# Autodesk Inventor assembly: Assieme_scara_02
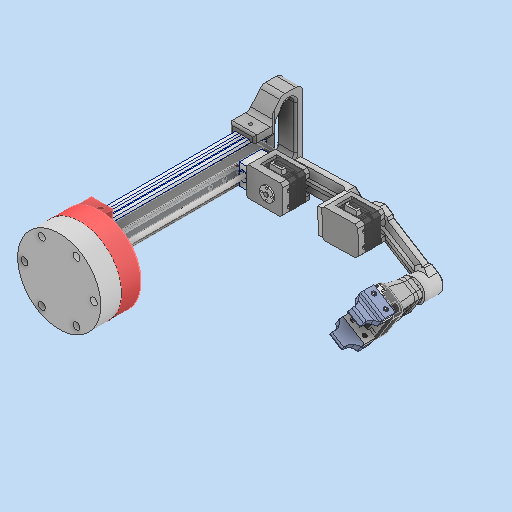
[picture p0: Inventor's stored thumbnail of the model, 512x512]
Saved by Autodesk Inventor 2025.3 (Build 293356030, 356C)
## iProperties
Created: 2025-11
Part Number: Assieme_scara_02
Document SubType Name: Assembly
Designer: Ryzen5700u
Title: Assieme_scara_03.stp
Author: R5800u
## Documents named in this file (14)
- C:\Users\R5800u\Desktop\scara_05\Assieme_scara_05.iam
- C:\Users\R5800u\Desktop\scara_05\base1.ipt
- C:\Users\R5800u\Desktop\scara_05\blocco_motore1.ipt
- C:\Users\R5800u\Desktop\scara_05\AS 1420 - 1973 - M4 x 30.ipt
- C:\Users\R5800u\Desktop\scara_05\tslot 2040.ipt
- C:\Users\R5800u\Desktop\scara_05\Assieme_profilato.iam
- C:\Users\R5800u\Desktop\scara_05\maniglia.ipt
- C:\Users\R5800u\Desktop\scara_05\disco_120.ipt
- C:\Users\R5800u\Desktop\scara_05\gripper v3.iam
- C:\Users\R5800u\Desktop\scara_05\nema17_23mm.ipt
- C:\Users\R5800u\Desktop\scara_05\braccio_nema17.ipt
- C:\Users\R5800u\Desktop\scara_05\blocco_motore2.ipt
- C:\Users\R5800u\Desktop\scara_05\braccio_2_nema17.ipt
- C:\Users\R5800u\Desktop\scara_05\DUOPAN-DG.ipt
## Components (17 placed, 13 different names)
1. base1:1
2. blocco_motore1:1
3. AS 1420 - Metrico M4 x 30:1
4. AS 1420 - Metrico M4 x 30:2
5. AS 1420 - Metrico M4 x 30:3
6. AS 1420 - Metrico M4 x 30:4
7. tslot 2040:1
8. Assieme_profilato:1 [sub-assembly] — Coincidente:3, Angolo:1, Coincidente:4, Angolo:2
9. maniglia:1
10. disco_120:1
11. gripper v3:1 [sub-assembly] — Rotazionale:3, Angolo:3
12. nema17_23mm:1 — Coincidente:5, Allineato:1, Coincidente:6, Rotazionale:1
13. braccio_nema17:1 — Rotazionale:1, Coincidente:9, Allineato:3, Angolo:2
14. blocco_motore2:1 — Coincidente:9, Allineato:3, Allineato:4
15. nema17_23mm:2 — Rotazionale:2
16. braccio_2_nema17:1 — Rotazionale:2, Rotazionale:3, Angolo:3
17. DUOPAN-DG:1 — Rotazionale:4
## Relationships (15: Mate 5, RevoluteJoint 4, Angle 3, Flush 3)
- Coincidente:3 [Mate]: Assieme_profilato:1
- Angolo:1 [Angle]: Assieme_profilato:1
- Coincidente:4 [Mate]: Assieme_profilato:1
- Coincidente:5 [Mate]: nema17_23mm:1
- Allineato:1 [Flush]: nema17_23mm:1
- Coincidente:6 [Mate]: nema17_23mm:1
- Rotazionale:1 [RevoluteJoint]: nema17_23mm:1 ↔ braccio_nema17:1
- Coincidente:9 [Mate]: braccio_nema17:1 ↔ blocco_motore2:1
- Allineato:3 [Flush]: braccio_nema17:1 ↔ blocco_motore2:1
- Rotazionale:2 [RevoluteJoint]: nema17_23mm:2 ↔ braccio_2_nema17:1
- Angolo:2 [Angle]: Assieme_profilato:1 ↔ braccio_nema17:1
- Allineato:4 [Flush]: blocco_motore2:1
- Rotazionale:3 [RevoluteJoint]: gripper v3:1 ↔ braccio_2_nema17:1
- Angolo:3 [Angle]: gripper v3:1 ↔ braccio_2_nema17:1
- Rotazionale:4 [RevoluteJoint]: DUOPAN-DG:1
## Named parameters: d86_d83 = 0, d87_d81 = 0, d88_d79 = 21.15 mm
